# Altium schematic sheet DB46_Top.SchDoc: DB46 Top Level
size A4; Organization: Altium Limited.; Address1: Level 3, 12a Rodborough Rd; Address2: Frenchs Forest 2086; Address3: NSW; Address4: AUSTRALIA; DocumentNumber: 1; SheetNumber: 2; SheetTotal: 23
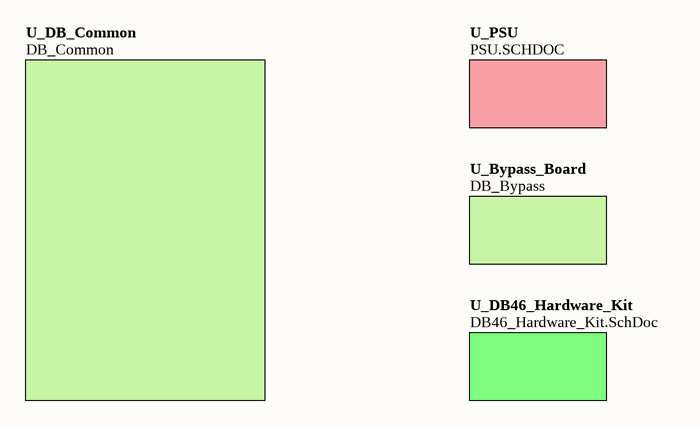
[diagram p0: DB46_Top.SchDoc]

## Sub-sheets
U_Bypass_Board = DB_Bypass: no entries
U_DB46_Hardware_Kit = DB46_Hardware_Kit.SchDoc: no entries
U_DB_Common = DB_Common: no entries
U_PSU = PSU.SCHDOC: no entries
